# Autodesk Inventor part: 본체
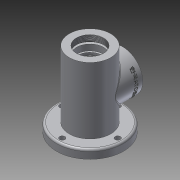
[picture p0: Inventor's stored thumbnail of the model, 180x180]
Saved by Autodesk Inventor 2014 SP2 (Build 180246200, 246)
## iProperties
Created: 2016-08
Part Number: 본체
Material: 알루미늄 6061
Document SubType Name: Modeling
Designer: 이도윤
Density: 2.71 g/cm^3
Appearance: 알루미늄 - 평지
Author: 이도윤
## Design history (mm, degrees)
sketch "스케치1"
  geometry: C1 r 31 at (0, 0); 1 further point
  constraints: 1 centre point, 1 coincident
  dimensions: "d0" = 62 diameter of C1
extrude "돌출1" new body sketch "스케치1" stored distance "d1" = 115; taper "d2" = 0 deg
sketch "스케치2"
  geometry: C1 r 31 at (0, 0) reference; 1 further point
  constraints: 1 coincident
hole "구멍1" sketch "스케치2" at (0, 0) diameter "d3" = 40.376; stored, may be unused: countersink angle "d7" = 90 deg, drill point angle "d9" = 0 deg; dims "d4" = 9, "d5" = 4, "d6" = 2, "d8" = 9
sketch "스케치3"
  geometry: C1 r 20.188 at (0, 0) reference; C2 r 24 at (0, 0)
  constraints: 1 centre point, 1 coincident
  dimensions: "d10" = 48 diameter of C2
extrude "돌출2" cut sketch "스케치3" distance "d11" = 3; taper "d12" = 0 deg
sketch "스케치4"
  geometry: C1 r 24 at (0, 0) reference; C2 r 20 at (0, 0)
  constraints: 1 centre point, 1 coincident
  dimensions: "d13" = 40 diameter of C2
extrude "돌출3" cut sketch "스케치4" distance "d14" = 9; taper "d15" = 0 deg
sketch "스케치5"
  geometry: C1 r 20 at (0, 0) reference; C2 r 17.5 at (0, 0)
  constraints: 1 centre point, 1 coincident
  dimensions: "d16" = 35 diameter of C2
extrude "돌출4" cut sketch "스케치5" distance "d17" = 3.25; taper "d18" = 0 deg
sketch "스케치6"
  geometry: C1 r 17.5 at (0, 0) reference; C2 r 18.5 at (0, 0)
  constraints: 1 centre point, 1 coincident
  dimensions: "d19" = 37 diameter of C2
extrude "돌출5" cut sketch "스케치6" distance "d20" = 1.75; taper "d21" = 0 deg
sketch "스케치8"
  geometry: C1 r 18.5 at (0, 0) reference; C2 r 17.5 at (0, 0)
  constraints: 1 centre point, 1 coincident
  dimensions: "d25" = 35 diameter of C2
extrude "돌출7" cut sketch "스케치8" distance "d26" = 20; taper "d27" = 0 deg
node "작업 평면1"
sketch "스케치9"
  geometry: L1 (31, 57.5)-(-31, 57.5) reference; C1 r 30 at (0, 1.5); 2 further points
  constraints: 1 centre point, 1 midpoint, 1 vertical alignment
  dimensions: "d30" = 60 diameter of C1; "d31" = 56 distance from line of C1.centre L1
extrude "돌출8" join sketch "스케치9" stored distance "d32" = 20; taper "d33" = 0 deg
node "작업 평면2"
sketch "스케치10"
  geometry: C1 r 26 at (0, 0); 1 further point
  constraints: 1 centre point, 1 coincident
  dimensions: "d35" = 52 diameter of C1
extrude "돌출9" cut sketch "스케치10" stored distance "d36" = 38; taper "d37" = 0 deg
sketch "스케치11"
  geometry: C1 r 26 at (0, 0) reference; C2 r 17.5 at (0, 0)
  constraints: 1 centre point, 1 coincident
  dimensions: "d38" = 35 diameter of C2
extrude "돌출10" cut sketch "스케치11" distance "d39" = 11; taper "d40" = 0 deg
sketch "스케치12"
  geometry: C1 r 30 at (0, 0) reference; C2 r 19 at (0, 0); 1 further point
  constraints: 1 centre point, 1 coincident
  dimensions: "d41" = 38 diameter of C2
extrude "돌출11" cut sketch "스케치12" distance "d42" = 45; taper "d43" = 0 deg
sketch "스케치13"
  geometry: C1 r 31 at (0, 0) reference; C2 r 21 at (0, 0)
  constraints: 1 centre point, 1 coincident
  dimensions: "d44" = 42 diameter of C2
node "작업 평면3"
sketch "스케치14"
  geometry: C1 r 16 at (0, 0); 1 further point
  constraints: 1 centre point, 1 coincident
  dimensions: "d46" = 32 diameter of C1
node "작업 평면4"
sketch "스케치15"
  geometry: C1 r 50 at (0, 0); C2 r 4 at (41.5, 0); C3 r 4 at (0, 41.5); C4 r 4 at (-41.5, 0); C5 r 4 at (0, -41.5); 1 further point
  constraints: 5 centre point, 1 coincident, 1 horizontal alignment, 9 other
  dimensions: "d48" = 100 diameter of C1; "d49" = 8 diameter of C2; "d50" = 41.5 distance of C2.centre point (0, 0); "d53" = 360 deg dimension on point (0, 0) C2.centre (derived)
extrude "돌출12" join sketch "스케치15" distance "d55" = 13; taper "d56" = 0 deg
feature "로프트1" dims "d57" = 0, "d58" = 90 deg, "d59" = 0, "d60" = 90 deg
sketch "스케치16"
  geometry: C1 r 17.5 at (0, 0) reference; C2 r 16.5 at (0, 0)
  constraints: 1 centre point, 1 coincident
  dimensions: "d61" = 33 diameter of C2
extrude "돌출13" cut sketch "스케치16" distance "d62" = 5; taper "d63" = 0 deg
sketch "스케치17"
  geometry: C1 r 16.5 at (0, 0) reference; C2 r 10 at (0, 0)
  constraints: 1 centre point, 1 coincident
  dimensions: "d64" = 20 diameter of C2
extrude "돌출14" cut sketch "스케치17" distance "d65" = 2.7; taper "d66" = 0 deg
sketch "스케치18"
  geometry: C1 r 10 at (0, 0) reference; C2 r 12.5 at (0, 0)
  constraints: 1 centre point, 1 coincident
  dimensions: "d67" = 25 diameter of C2
extrude "돌출15" cut sketch "스케치18" distance "d68" = 7.3; taper "d69" = 0 deg
sketch "스케치19"
  geometry: C1 r 19 at (0, 0) reference; 5 further points
  constraints: 1 vertical alignment, 5 other
  dimensions: "d70" = 24 distance of point (0, 24) C1.centre; "d73" = 360 deg dimension on C1.centre point (0, 24) (derived)
hole "구멍2" sketch "스케치19" at (0, 24), (-24, 0), (0, -24), (24, 0) diameter "d75" = 3.242; stored, may be unused: countersink angle "d79" = 90 deg, drill point angle "d81" = 118 deg; dims "d76" = 8, "d77" = 4, "d78" = 2, "d80" = 10
fillet "모깎기1" dims "d82" = 3
fillet "모깎기2" dims "d83" = 3
fillet "모깎기3" dims "d84" = 0.3
chamfer "모따기1" distance "d85" = 0.7; stored, may be unused: second distance "d86" = 2, angle "d87" = 30 deg
chamfer "모따기2" distance "d88" = 1; stored, may be unused: second distance "d89" = 2, angle "d90" = 30 deg
node "작업 평면5"
sketch "스케치20"
  geometry: L1 (49, 31.5)-(49, -28.5) reference; L2 (31, 57.5)-(-31, 57.5) reference; 2 further points
  constraints: 1 other
  dimensions: "d92" = 10 distance from line of L1 point (39, 1.5); "d93" = 56 distance from line of point (39, 1.5) L2
feature "엠보싱1" sketch "스케치20" dims "d0" = 62, "d94" = 0.5, "d95" = 0
chamfer "모따기3" distance "d96" = 1; stored, may be unused: second distance "d97" = 2, angle "d98" = 45 deg
node "솔리드1"
other parameters: "d28" = 49, "d34" = -56, "d45" = -14, "d47" = -3
